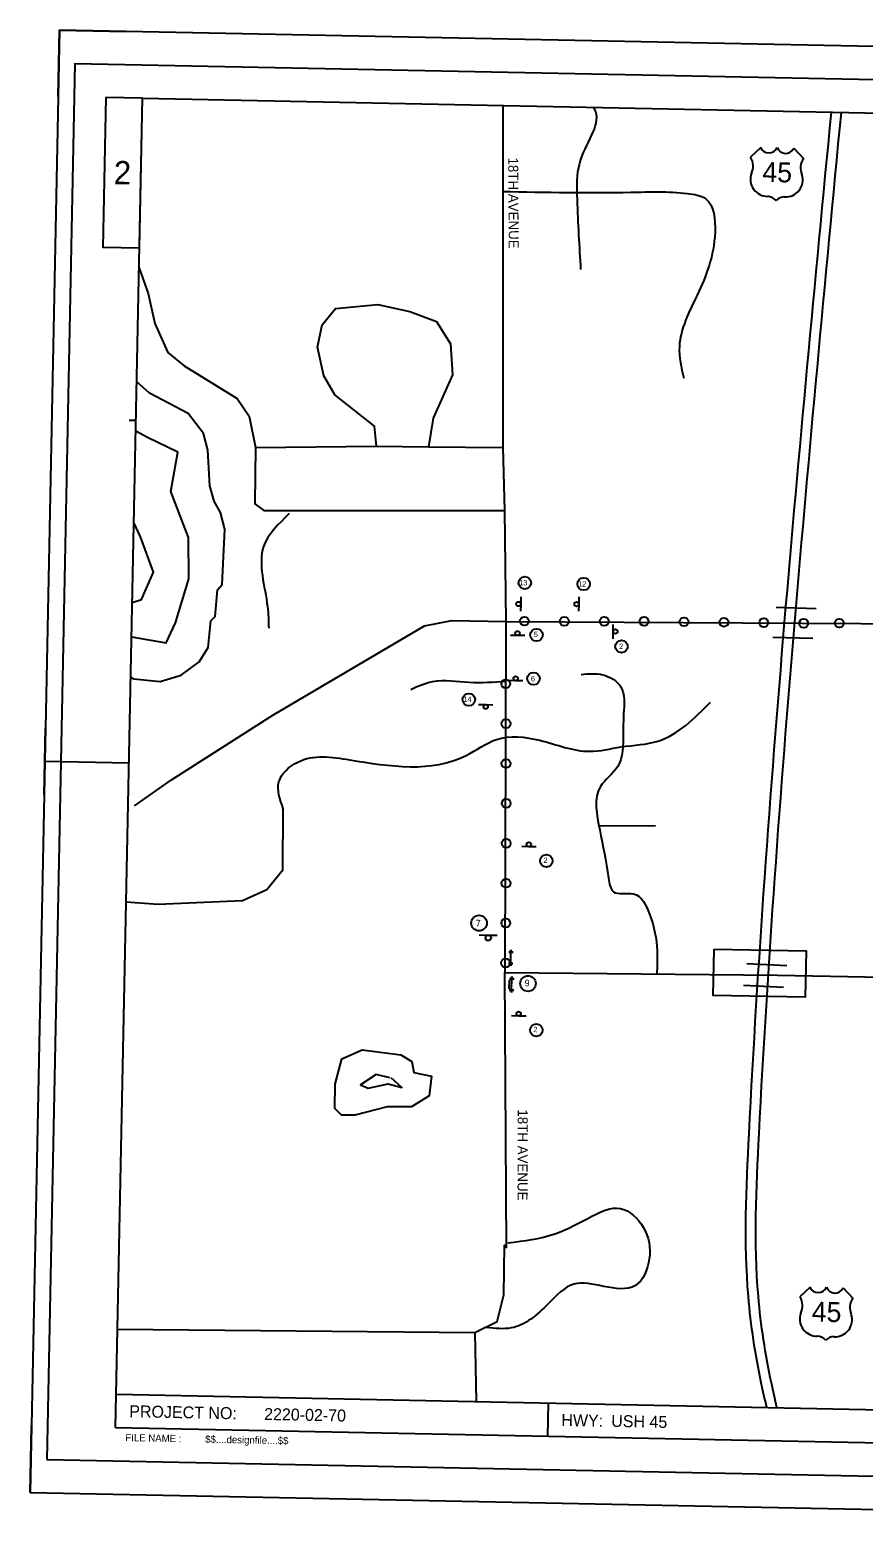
# Model space of a CAD drawing. Extents: x 299354 to 1325680, y 96128 to 228242.
# Drawn here: x 1308462 to 1314730, y 143563 to 154903 of the extents above; entities that cross this region are included whole.
import ezdxf

# ---------------------------------------------------------------- set-up
doc = ezdxf.new("R2010")
doc.units = 0
for name, color, linetype in [('CA-TEXT', 7, 'Continuous'), ('CE-TOPO-CONC-SLAB', 7, 'Continuous'), ('Level 2', 7, 'Continuous'), ('Level 3', 7, 'Continuous'), ('Level 4', 7, 'Continuous'), ('Level 56', 7, 'Continuous'), ('P_TC', 7, 'Continuous'), ('PLT_Sheet_Border', 7, 'Continuous'), ('PLT_Sheet_Info', 7, 'Continuous'), ('SIGNS-POLES', 7, 'Continuous')]:
    doc.layers.add(name, color=color, linetype=linetype)

msp = doc.modelspace()

# ---------------------------------------------------------------- linework, layer by layer
at = {"layer": 'CA-TEXT'}
for p, q in [((1313955, 154021), (1313879, 153948)), ((1314203, 154015), (1314276, 153939)), ((1314080, 153841), (1314080, 153841)), ((1314326, 145449), (1314250, 145376)), ((1314574, 145443), (1314647, 145366)), ((1314451, 145269), (1314451, 145269))]:
    msp.add_line(p, q, dxfattribs=at)
for centre, radius in [((1312181, 150746), 46.9), ((1312623, 150738), 46.9), ((1312269, 150354), 46.9), ((1312908, 150267), 46.9), ((1312246, 150026), 46.9), ((1311760, 149868), 46.9), ((1312343, 148655), 46.9), ((1311837, 148187), 58.6), ((1312205, 147732), 58.6), ((1312267, 147382), 46.9)]:
    msp.add_circle(centre, radius, dxfattribs=at)
for centre, radius, start, end in [((1314016, 154048), 68.5, 203.6963, 335.6477), ((1314142, 154045), 68.5, 201.8862, 333.8376), ((1313769, 153881), 129, 334.5713, 31.4533), ((1314383, 153867), 129, 146.0806, 202.9627), ((1314006, 153782), 129, 159.8617, 270.9574), ((1314142, 153778), 129, 266.5765, 17.6722), ((1314001, 153559), 94.4, 42.5398, 87.5237), ((1314137, 153555), 94.4, 90.0102, 134.044), ((1314387, 145476), 68.5, 203.6963, 335.6477), ((1314513, 145473), 68.5, 201.8862, 333.8376), ((1314140, 145309), 129, 334.5713, 31.4533), ((1314754, 145295), 129, 146.0806, 202.9627), ((1314377, 145209), 129, 159.8617, 270.9574), ((1314513, 145205), 129, 266.5765, 17.6722), ((1314373, 144986), 94.4, 42.5398, 87.5237), ((1314508, 144982), 94.4, 90.0102, 134.044)]:
    msp.add_arc(centre, radius, start, end, dxfattribs=at)
at = {"layer": 'CE-TOPO-CONC-SLAB'}
for centre in [(1312178, 150458), (1312478, 150457), (1312778, 150457), (1313078, 150456), (1313378, 150453), (1313678, 150450), (1313978, 150446), (1314278, 150441), (1314546, 150443), (1312038, 149987), (1312039, 149687), (1312040, 149387), (1312041, 149087), (1312041, 148787), (1312040, 148487), (1312038, 148187), (1312036, 147887)]:
    msp.add_circle(centre, 33.5, dxfattribs=at)
at = {"layer": 'Level 2'}
for points in [[(1314000, 144544), (1313959, 144729), (1313862, 145380), (1313867, 146601), (1314486, 154286)], [(1314076, 144543), (1314035, 144729), (1313937, 145380), (1313942, 146601), (1314561, 154284)]]:
    msp.add_spline(points, degree=3, dxfattribs=at)
at = {"layer": 'Level 3'}
for p, q in [((1314072, 150562), (1314372, 150554)), ((1314105, 150473), (1314105, 150473)), ((1314047, 150337), (1314347, 150329))]:
    msp.add_line(p, q, dxfattribs=at)
for points in [[(1310286, 149750), (1311427, 150422), (1311632, 150462), (1312037, 150456)], [(1312037, 150456), (1317378, 150425)], [(1309524, 149264), (1310286, 149750)], [(1309245, 149069), (1309524, 149264)]]:
    msp.add_lwpolyline(points, dxfattribs=at)
at = {"layer": 'Level 4'}
for p, q in [((1312744, 148920), (1313164, 148918)), ((1313851, 147882), (1314151, 147867)), ((1313943, 147871), (1313943, 147871)), ((1313825, 147719), (1314125, 147704))]:
    msp.add_line(p, q, dxfattribs=at)
for points in [[(1312016, 154332), (1312016, 151765)], [(1309280, 153114), (1309350, 152922), (1309398, 152697), (1309496, 152479), (1309620, 152378), (1310018, 152133), (1310108, 151999), (1310156, 151765)], [(1311065, 151774), (1311050, 151924), (1310752, 152160), (1310670, 152302), (1310622, 152519), (1310657, 152686), (1310758, 152810), (1311075, 152840), (1311317, 152788), (1311516, 152711), (1311623, 152544), (1311638, 152310), (1311493, 151986), (1311457, 151770)], [(1310156, 151765), (1310152, 151340), (1310219, 151290)], [(1310156, 151765), (1311065, 151774)], [(1311065, 151774), (1311457, 151770)], [(1311457, 151770), (1312016, 151765)], [(1312016, 151765), (1312028, 151290)], [(1310219, 151290), (1312028, 151290)], [(1312028, 151290), (1312037, 150456)], [(1312037, 150456), (1312030, 147815)], [(1309184, 148346), (1309424, 148330), (1310058, 148358), (1310242, 148439), (1310361, 148588), (1310365, 149047)], [(1311805, 145108), (1311972, 145190), (1312024, 145390), (1312027, 145765), (1312044, 145748), (1312030, 147815)], [(1312030, 147815), (1314081, 147796), (1317375, 147733)], [(1309119, 145133), (1311805, 145108)], [(1311805, 145108), (1311815, 144588)]]:
    msp.add_lwpolyline(points, dxfattribs=at)
for points in [[(1312603, 153102), (1312576, 153629), (1312594, 153904), (1312686, 154116), (1312714, 154290), (1312699, 154322)], [(1312013, 153690), (1312978, 153684), (1313404, 153675), (1313541, 153635), (1313611, 153383), (1313476, 152909), (1313343, 152523), (1313376, 152285)], [(1310410, 151267), (1310217, 151020), (1310246, 150568), (1310255, 150405)], [(1312604, 150057), (1312767, 150054), (1312903, 149963), (1312924, 149762), (1312921, 149612), (1312878, 149362), (1312750, 149214), (1312744, 148889), (1312811, 148524), (1312847, 148423), (1312997, 148407), (1313119, 148254), (1313176, 147978), (1313173, 147802)], [(1311324, 149945), (1311488, 150004), (1311763, 149999), (1312039, 150006)], [(1310365, 149047), (1310332, 149250), (1310473, 149398), (1310862, 149415), (1311740, 149448), (1311968, 149568), (1312293, 149562), (1312668, 149479), (1312906, 149512), (1313183, 149556), (1313577, 149849)], [(1312054, 145782), (1312407, 145850), (1312685, 145982), (1312899, 146041), (1313072, 145899), (1313117, 145660), (1313013, 145462), (1312775, 145454), (1312549, 145471), (1312358, 145325), (1312079, 145142), (1311891, 145146)]]:
    msp.add_spline(points, degree=3, dxfattribs=at)
at = {"layer": 'Level 56'}
for points in [[(1309218, 150037), (1309240, 150023), (1309440, 150005), (1309598, 150053), (1309733, 150152), (1309800, 150260), (1309819, 150460), (1309853, 150493), (1309871, 150693), (1309905, 150734), (1309925, 151151), (1309893, 151276), (1309844, 151360), (1309812, 151477), (1309797, 151743), (1309765, 151869), (1309650, 152020), (1309359, 152172), (1309262, 152260)], [(1309224, 150340), (1309483, 150296), (1309555, 150445), (1309655, 150776), (1309651, 151086), (1309520, 151434), (1309573, 151730), (1309345, 151840), (1309255, 151886)], [(1309229, 150598), (1309299, 150620), (1309390, 150827), (1309292, 151091), (1309241, 151199)], [(1311167, 147022), (1311062, 147048), (1310945, 146971), (1311004, 146946), (1311153, 146977), (1311257, 146951), (1311177, 147022)]]:
    msp.add_lwpolyline(points, dxfattribs=at)
msp.add_lwpolyline([(1311328, 146804), (1311145, 146806), (1310902, 146742), (1310802, 146743), (1310753, 146793), (1310754, 146976), (1310806, 147167), (1310957, 147233), (1311248, 147197), (1311331, 147146), (1311347, 147063), (1311480, 147036), (1311462, 146887)], close=True, dxfattribs=at)
at = {"layer": 'P_TC'}
for p, q in [((1312075, 147883), (1312058, 147883)), ((1312058, 147883), (1312075, 147883)), ((1312077, 147968), (1312060, 147968)), ((1312060, 147968), (1312077, 147968)), ((1312075, 147883), (1312077, 147968)), ((1312092, 147883), (1312075, 147883)), ((1312075, 147883), (1312092, 147883)), ((1312075, 147883), (1312075, 147866)), ((1312075, 147866), (1312075, 147883)), ((1312077, 147968), (1312077, 147985)), ((1312077, 147985), (1312077, 147968)), ((1312077, 147968), (1312094, 147968)), ((1312094, 147968), (1312077, 147968)), ((1312083, 147768), (1312066, 147768)), ((1312066, 147768), (1312083, 147768)), ((1312081, 147683), (1312083, 147768)), ((1312083, 147768), (1312083, 147785)), ((1312083, 147785), (1312083, 147768)), ((1312083, 147768), (1312100, 147767)), ((1312100, 147767), (1312083, 147768)), ((1312064, 147693), (1312065, 147758)), ((1312081, 147683), (1312064, 147683)), ((1312064, 147683), (1312081, 147683)), ((1312098, 147682), (1312081, 147683)), ((1312081, 147683), (1312098, 147682)), ((1312081, 147683), (1312081, 147666)), ((1312081, 147666), (1312081, 147683))]:
    msp.add_line(p, q, dxfattribs=at)
msp.add_lwpolyline([(1313605, 147992), (1314297, 147978), (1314290, 147629), (1313598, 147643)], close=True, dxfattribs=at)
msp.add_lwpolyline([(1313605, 147992), (1314297, 147978), (1314290, 147629), (1313598, 147643)], close=True, dxfattribs=at)
at = {"layer": 'PLT_Sheet_Border'}
for points in [[(1308462, 143905), (1325458, 143563), (1325680, 154561), (1308683, 154903)], [(1308587, 144153), (1325133, 143820), (1325345, 154318), (1308798, 154651)]]:
    msp.add_lwpolyline(points, close=True, dxfattribs=at)
at = {"layer": 'PLT_Sheet_Info'}
for p, q in [((1308673, 154403), (1308683, 154903)), ((1308683, 154903), (1309183, 154893)), ((1309104, 144393), (1309305, 154391)), ((1309305, 154391), (1325052, 154073)), ((1309257, 151966), (1309207, 151967)), ((1308567, 149154), (1308577, 149654)), ((1308572, 149404), (1309205, 149392)), ((1309580, 149384), (1309580, 149384)), ((1309109, 144643), (1324856, 144325)), ((1312353, 144327), (1312358, 144577)), ((1308462, 143905), (1308472, 144405)), ((1309104, 144393), (1324851, 144075)), ((1308462, 143905), (1308961, 143895))]:
    msp.add_line(p, q, dxfattribs=at)
msp.add_lwpolyline([(1309305, 154391), (1309030, 154396), (1309008, 153271), (1309283, 153266)], close=True, dxfattribs=at)
at = {"layer": 'SIGNS-POLES'}
for p, q in [((1312151, 150641), (1312150, 150587)), ((1312588, 150641), (1312587, 150587)), ((1312150, 150587), (1312148, 150533)), ((1312587, 150587), (1312585, 150533)), ((1312846, 150325), (1312845, 150379)), ((1312846, 150380), (1312846, 150434)), ((1312127, 150351), (1312073, 150351)), ((1312181, 150350), (1312127, 150350)), ((1312113, 150010), (1312059, 150011)), ((1312167, 150010), (1312113, 150010)), ((1311832, 149832), (1311886, 149831)), ((1311887, 149830), (1311941, 149828)), ((1312212, 148761), (1312158, 148762)), ((1312266, 148761), (1312212, 148761)), ((1311838, 148098), (1311906, 148097)), ((1311906, 148097), (1311974, 148095)), ((1312136, 147488), (1312082, 147489)), ((1312190, 147488), (1312136, 147488))]:
    msp.add_line(p, q, dxfattribs=at)
for centre, radius in [((1312133, 150587), 16.7), ((1312570, 150586), 16.7), ((1312126, 150367), 16.7), ((1312862, 150380), 16.7), ((1312112, 150027), 16.7), ((1311887, 149814), 16.7), ((1312211, 148778), 16.7), ((1311906, 148076), 20.9), ((1312135, 147505), 16.7)]:
    msp.add_circle(centre, radius, dxfattribs=at)

# ---------------------------------------------------------------- texts
at = {"layer": 'CA-TEXT'}
for s, height, rotation, p in [('18TH AVENUE', 75, 270.3214, (1312056, 153945)), ('45', 150, 358.767, (1313966, 153762)), ('13', 40, 358.8468, (1312138, 150728)), ('12', 40, 358.8468, (1312581, 150719)), ('5', 40, 358.8468, (1312248, 150339)), ('2', 40, 358.8468, (1312889, 150249)), ('6', 40, 358.8468, (1312226, 150005)), ('14', 40, 358.8468, (1311719, 149851)), ('2', 40, 358.8468, (1312321, 148640)), ('7', 50, 358.8468, (1311812, 148162)), ('9', 50, 358.8468, (1312179, 147712)), ('2', 40, 358.8468, (1312245, 147367)), ('18TH AVENUE', 75, 269.8329, (1312128, 146786)), ('45', 150, 358.767, (1314337, 145190))]:
    msp.add_text(s, height=height, rotation=rotation, dxfattribs=at).set_placement(p)
at = {"layer": 'PLT_Sheet_Info'}
for s, height, p in [('2', 175, (1309089, 153745)), ('PROJECT NO:', 90, (1309206, 144471)), ('2220-02-70', 90, (1310220, 144450)), ('HWY:', 90, (1312455, 144405)), ('USH 45          ', 90, (1312830, 144398)), ('FILE NAME :', 54, (1309177, 144291)), ('$$....designfile....$$', 54, (1309777, 144279))]:
    msp.add_text(s, height=height, rotation=358.8462, dxfattribs=at).set_placement(p)

doc.saveas('drawing.dxf')
